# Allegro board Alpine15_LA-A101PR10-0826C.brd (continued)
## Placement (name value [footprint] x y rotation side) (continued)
CV2405  0.1U_0402_10V7K~D  [C_0402]  68.29 87.71 180 top
CV2406  0.1U_0402_10V7K~D  [C_0402]  68.29 85.87 180 top
CV2407  0.1U_0402_10V7K~D  [C_0402]  68.29 86.82 180 top
CV2408  0.1U_0402_10V7K~D  [C_0402]  65.36 82.69 180 top
CV2901  0.01U_0402_16V7K~D  [C_0402]  33.82 115.99 180 bottom
CV2902  0.01U_0402_16V7K~D  [C_0402]  31.81 113.17 0 top
CV2918  10U_0603_6.3V6M~D  [C_0603]  39.38 113.36 0 top
CV2919  10U_0603_6.3V6M~D  [C_0603]  39.51 113.36 180 bottom
CV2920  10U_0603_6.3V6M~D  [C_0603]  39.44 85.1 0 bottom
CV2921  10U_0603_6.3V6M~D  [C_0603]  25.22 94.69 90 top
CV2926  1U_0402_6.3V6K~D  [C_0402]  35.4 101 180 top
CV2927  1U_0402_6.3V6K~D  [C_0402]  36.47 114.12 180 top
CV2928  1U_0402_6.3V6K~D  [C_0402]  37.21 84.34 0 bottom
CV2929  1U_0402_6.3V6K~D  [C_0402]  28.64 101.04 180 top
CV2930  1U_0402_6.3V6K~D  [C_0402]  29.17 113.17 180 top
CV2931  1U_0402_6.3V6K~D  [C_0402]  38.41 101.11 0 top
CV2932  1U_0402_6.3V6K~D  [C_0402]  30.03 113.17 0 top
CV2933  1U_0402_6.3V6K~D  [C_0402]  38.44 113.17 180 top
CV2934  0.1U_0402_10V7K~D  [C_0402]  38.41 100.15 0 top
CV2935  0.1U_0402_10V7K~D  [C_0402]  36.47 113.17 180 top
CV2936  0.1U_0402_10V7K~D  [C_0402]  29.91 101.04 0 top
CV2937  0.1U_0402_10V7K~D  [C_0402]  37.17 100.98 180 top
CV2938  0.1U_0402_10V7K~D  [C_0402]  38.44 114.12 180 top
CV2939  0.1U_0402_10V7K~D  [C_0402]  37.17 100.03 180 top
CV2940  0.1U_0402_10V7K~D  [C_0402]  36.98 113.17 180 bottom
CV2941  0.01U_0402_16V7K~D  [C_0402]  33.59 113.17 0 top
CV2942  0.01U_0402_16V7K~D  [C_0402]  31.18 85.23 0 top
CV2943  0.01U_0402_16V7K~D  [C_0402]  33.4 97.61 0 top
CV2944  0.01U_0402_16V7K~D  [C_0402]  36.47 83.45 90 top
CV2945  0.1U_0402_10V7K~D  [C_0402]  28.28 113.17 180 bottom
CV2946  0.1U_0402_10V7K~D  [C_0402]  29.14 113.17 0 bottom
CV2947  0.1U_0402_10V7K~D  [C_0402]  28.28 114.06 180 bottom
CV2948  0.1U_0402_10V7K~D  [C_0402]  29.14 114.06 0 bottom
CV2949  0.1U_0402_10V7K~D  [C_0402]  29.17 114.06 180 top
CV2950  1U_0402_6.3V6K~D  [C_0402]  30.03 114.06 0 top
CV2951  1U_0402_6.3V6K~D  [C_0402]  30.29 84.28 0 bottom
CV2952  1U_0402_6.3V6K~D  [C_0402]  27.58 85.23 180 bottom
CV2953  0.1U_0402_10V7K~D  [C_0402]  35.58 84.34 180 bottom
CV2954  0.1U_0402_10V7K~D  [C_0402]  27.58 84.28 180 bottom
CV2955  0.1U_0402_10V7K~D  [C_0402]  30.29 85.23 0 bottom
CV2956  0.1U_0402_10V7K~D  [C_0402]  37.21 85.23 0 bottom
CV2957  0.1U_0402_10V7K~D  [C_0402]  35.58 85.23 180 bottom
CV2958  0.1U_0402_10V7K~D  [C_0402]  28.45 84.28 0 bottom
CV2959  1U_0402_6.3V6K~D  [C_0402]  28.45 85.23 0 bottom
CV2960  1U_0402_6.3V6K~D  [C_0402]  37.3 98.31 180 top
CV2961  1U_0402_6.3V6K~D  [C_0402]  27.58 84.28 180 top
CV2962  1U_0402_6.3V6K~D  [C_0402]  37.3 97.42 180 top
CV2963  0.1U_0402_10V7K~D  [C_0402]  38.41 97.36 0 top
CV2964  0.1U_0402_10V7K~D  [C_0402]  27.58 85.23 180 top
CV2965  0.1U_0402_10V7K~D  [C_0402]  38.41 99.2 0 top
CV2966  0.1U_0402_10V7K~D  [C_0402]  28.45 85.23 0 top
CV2967  0.1U_0402_10V7K~D  [C_0402]  30.24 85.24 270 top
CV2968  0.1U_0402_10V7K~D  [C_0402]  28.45 84.28 0 top
CV2969  1U_0402_6.3V6K~D  [C_0402]  38.41 98.25 0 top
CV3047  22U_0805_6.3V6M~D  [C_0805]  60.67 89.61 0 top
CV3048  4.7U_0603_6.3V6K~D  [C_0603]  60.28 92.09 0 top
CV3049  22U_0805_6.3V6M~D  [C_0805]  57.83 89.8 0 top
CV3050  22U_0805_6.3V6M~D  [C_0805]  54.91 89.8 0 top
CV3051  4.7U_0603_6.3V6K~D  [C_0603]  50 84.11 0 bottom
CV3052  22U_0805_6.3V6M~D  [C_0805]  52.91 80.24 0 top
CV3053  4.7U_0603_6.3V6K~D  [C_0603]  70.11 91.2 270 top
CV3054  4.7U_0603_6.3V6K~D  [C_0603]  66.31 94.63 90 top
CV3056  4.7U_0603_6.3V6K~D  [C_0603]  52.54 84.87 0 top
CV3057  22U_0805_6.3V6M~D  [C_0805]  53.33 86.69 0 top
CV3058  4.7U_0603_6.3V6K~D  [C_0603]  46.13 116.55 90 bottom
CV3059  22U_0805_6.3V6M~D  [C_0805]  51.46 116.53 90 bottom
CV3060  4.7U_0603_6.3V6K~D  [C_0603]  47.52 116.55 90 bottom
CV3061  4.7U_0603_6.3V6K~D  [C_0603]  61.48 106.19 90 top
CV3062  4.7U_0603_6.3V6K~D  [C_0603]  68.22 100.55 270 top
CV3063  22U_0805_6.3V6M~D  [C_0805]  69.87 100.45 270 top
CV3064  22U_0805_6.3V6M~D  [C_0805]  68.72 103.68 90 top
D1  RB751S40T1_SOD523-2~D  [RB751S40T1_SOD523-2]  17.23 119.29 180 bottom
D2  AZ5125-02S.R7G_SOT23-3  [AZ5125-02SPR7G_SOT23-3]  329.45 160.02 270 top
D12  RB751S40T1_SOD523-2~D  [RB751S40T1_SOD523-2]  311.17 176.19 0 bottom
D13  RB751S40T1_SOD523-2~D  [RB751S40T1_SOD523-2]  320.59 182.93 180 top
D14  RB751S40T1_SOD523-2~D  [RB751S40T1_SOD523-2]  328.95 176.12 90 bottom
D17  IP4292CZ10-TBR_XSON10_2.5X1~D  [IP4292CZ10-TBR_XSON10_2P5X1]  16.77 77.86 90 bottom
D18  PESD5V0U2BT_SOT23-3~D  [PESD5V0U2BT_SOT23-3]  16.6 80.83 270 top
D19  RB751S40T1_SOD523-2~D  [RB751S40T1_SOD523-2]  202.14 183.82 270 top
D20  PESD24VS2UT_SOT23-3~D  [PESD24VS2UT_SOT23-3]  151.65 183.45 0 bottom
D22  PESD5V0U2BT_SOT23-3~D  [PESD5V0U2BT_SOT23-3]  143.03 104.14 90 top
D23  RB751S40T1_SOD523-2~D  [RB751S40T1_SOD523-2]  220.68 39.03 0 top
D24  RB751S40T1_SOD523-2~D  [RB751S40T1_SOD523-2]  220.68 40.42 0 top
D27  -  [L30ESD24VC3-2_SOT23-3]  307.1 166 0 top
D65  RB751VM-40TE-17_SOD323-2~D  [RB751VM-40TE-17_SOD323-2]  14.05 102.35 0 top
D76  -  [BAT54CW_SOT323-3]  95.18 142.53 90 bottom
D77  PESD5V0U2BT_SOT23-3~D  [PESD5V0U2BT_SOT23-3]  104.54 158.03 90 top
D78  PESD5V0U2BT_SOT23-3~D  [PESD5V0U2BT_SOT23-3]  200.78 87.97 90 top
D79  -  [BAT54CW_SOT323-3]  129.18 124.5 270 top
D80  -  [BAT54CW_SOT323-3]  141.11 110.36 180 top
D87  PESD5V0U2BT_SOT23-3~D  [PESD5V0U2BT_SOT23-3]  208.96 170.73 90 top
D88  -  [L30ESDL5V0C3-2_SOT23-3]  99.58 164.78 0 bottom
DE1  -  [PESD5V0U2BT_SOT23-3]  234.63 131.58 90 top
DE2  -  [PESD5V0U2BT_SOT23-3]  234.63 127.62 90 top
FD1  FIDUCIAL MARK~D  [FIDUCIAL_C40M80]  5.3 10.32 180 bottom
FD2  FIDUCIAL MARK~D  [FIDUCIAL_C40M80]  86.38 185 0 top
FD3  FIDUCIAL MARK~D  [FIDUCIAL_C40M80]  225.67 12.64 0 top
FD4  FIDUCIAL MARK~D  [FIDUCIAL_C40M80]  328.23 145.3 180 bottom
H1  -  [H_4P4]  110.67 85.22 270 top
H2  -  [H_3P8]  110.67 65.22 90 top
H3  -  [H_4P4]  176.67 85.22 0 top
H4  -  [H_4P4]  176.67 65.22 0 top
H5  -  [H_3P8]  42.4 74.36 0 top
H6  -  [H_4P4]  77.58 125.33 0 top
H7  -  [H_3P0]  83.23 165.1 90 top
H8  -  [H_3P0]  141.7 177.95 90 top
H9  -  [H_3P0]  186.13 67.27 0 top
H10  -  [H_3P0]  6.12 117.82 0 top
H11  -  [H_3P0]  101.98 117.88 0 top
H12  -  [H_3P0]  231.9 108.6 0 top
H13  -  [H_3P0]  30.2 71.1 0 top
H14  -  [H_3P0]  229.7 177.95 90 top
H15  -  [H_3P0]  232.2 65.5 0 top
H16  -  [H_3P0]  11.8 3 0 top
H17  -  [H_3P0]  232.2 10.51 0 top
H18  -  [H_3P3]  341.9 186.6 0 top
H19  -  [H_3P3]  333.9 149.1 0 top
H20  -  [H_3P0]  188.2 3 0 top
H21  -  [H_2P5X4P0]  234.15 101.64 90 top
H22  -  [H_2P5X4P0]  82.23 182.21 0 top
H23  -  [H_1P2]  18.2 69.1 0 top
H24  -  [H_1P2]  89.98 61.52 0 top
H25  -  [H_1P2]  79.82 18.29 0 top
H26  -  [H_1P2]  286.35 165.2 0 top
H27  -  [H_1P2]  325.81 160.11 0 top
H28  -  [H_2P5X3P5]  6.3 3 90 top
H36  -  [H_3P3]  212.72 62.18 0 top
H37  -  [H_3P3]  106.7 164.1 0 top
H40  -  [H_3P0]  79.57 140.89 0 top
H41  -  [H_2P5N]  340.7 144.71 0 top
HDMIU1  -  [AP2330W-7_SC59-3]  16.65 99.61 270 top
JAPS1  ACES_50506-01841-P01  [ACES_50506-01841-P01_18P]  224.85 72.59 90 top
JBIO1  ACES_51524-0060N-001  [ACES_51524-0060N-001_6P]  203.26 85.1 90 top
JBT1  ACES_50273-0020N-001  [ACES_50273-0020N-001_2P-T]  12.19 22.48 90 bottom
JDEG1  TYCO_1-2041070-0~D  [TYCO_1-2041070-0_10P]  224.6 91.55 270 top
JDIMM1  CONCR_0706E0BE40F  [CONCR_0706E0BE40F_204P]  87.98 26.43 0 bottom
JDIMM2  CONCR_0706E0BE40F  [CONCR_0706E0BE40F_204P]  162.48 26.43 0 bottom
JDOCK1  JAE_WD2F144WB3R300~D  [JAE_WD2F144WB3R300_144P]  166.95 176.6 0 bottom
JEXP1  E&T_1001K-F40C-03L  [E-T_1001K-F40C-03L_40P]  97.12 22.67 0 top
JFAN1  ACES_50281-0040N-001  [ACES_50281-0040N-001_4P]  17.07 110.63 180 top
JHDMI1  CONCR_099BTAC19NBLCNF  [CONCR_099BTAC19NBLCNF_19P]  9.95 98.25 90 bottom
JIO1  E-T_1000-F80E-01L  [E-T_1000-F80E-01L_80P]  335.67 177.95 270 bottom
JKB1  ACES_51524-01001-003  [ACES_51524-01001-003_10P]  212.64 104.63 180 top
JLED1  ACES_51522-01201-001  [ACES_51522-01201-001_12P]  215.36 33.56 0 top
JLVDS1  ACES_50398-04071-001  [ACES_50398-04071-001_40P]  99.13 160.45 90 top
JMED1  ACES_51522-00601-001  [ACES_51522-00601-001_6P]  99.85 180.75 270 top
JMINI1  ACES_51700-0520W-001  [ACES_51700-0520W-001_52P]  301.9 188.2 0 bottom
JMINI2  LOTES_AAA-PCI-041-K01  [LOTES_AAA-PCI-041-K01_52P]  234.1 141.3 90 bottom
JPWR1  ACES_51522-01001-001  [ACES_51522-01001-001_10P]  314.75 169.02 180 top
JSATA1  J-L_TNBNRACB0007022  [J-L_TNBNRACB0007022_22P-T]  219.68 137 90 bottom
JSATA2  SANTA_201902-1  [SANTA_201902-1_13P]  237.54 22.21 270 bottom
JSD1  ALPS_SCDADA0101_NR  [ALPS_SCDADA0101_19P]  30.28 45.1 90 bottom
JSIM1  PROCO_879J-N006-00A0  [PROCO_879J-N006-00A0_8P]  258.99 186.49 0 bottom
JSPK1  ACES_50273-00401-001  [ACES_50273-00401-001_4P]  228.2 127.1 0 bottom
JTAA1  ACES_50051-02071-001  [ACES_50051-02071-001_20P-T]  206.01 76.23 0 bottom
JTAG1  @SHORT PADS~D  [SHORTPADS]  153.94 123.1 180 top
JTP1  ACES_51522-00801-001  [ACES_51522-00801-001_8P]  130.4 106.35 0 top
JTS1  E-T_4260K-Q06N-23L  [E-T_4260K-Q06N-23L_6P]  98.39 167.09 270 top
JUDB1  ACES_51522-02001-P02  [ACES_51522-02001-P02_20P]  107.65 134.27 270 top
JUSB1  SANTA_373130-1  [SANTA_373130-1_9P]  14.32 84.1 90 bottom
JXDP1  SAMTE_BSH-030-01-L-D-A  [SAMTE_BSH-030-01-L-D-A_60P]  95.21 37.36 90 top
L1  BLM18AG102SN1D_2P~D  [MURAT_BLM18AG102SN1D_2P]  177.34 170.34 0 bottom
L2  BLM18AG102SN1D_2P~D  [MURAT_BLM18AG102SN1D_2P]  180.23 168.09 90 bottom
L4  BLM18AG102SN1D_2P~D  [MURAT_BLM18AG102SN1D_2P]  177.39 168.82 0 bottom
L5  BLM18AG102SN1D_2P~D  [MURAT_BLM18AG102SN1D_2P]  174.68 168.31 0 bottom
L9  0_0402_5%~D  [R_0402]  15.61 103.39 180 bottom
L10  DLW21SN900HQ2L_0805_4P~D  [MURAT_DLW21SN900HQ2L_0805_4P]  16.01 103.39 180 bottom
L11  0_0402_5%~D  [R_0402]  15.61 104.25 180 bottom
L12  0_0402_5%~D  [R_0402]  15.66 106.74 180 bottom
L13  DLW21SN900HQ2L_0805_4P~D  [MURAT_DLW21SN900HQ2L_0805_4P]  16.05 106.77 180 bottom
L14  0_0402_5%~D  [R_0402]  15.66 107.63 180 bottom
L15  0_0402_5%~D  [R_0402]  15.61 100.77 180 bottom
L16  DLW21SN900HQ2L_0805_4P~D  [MURAT_DLW21SN900HQ2L_0805_4P]  16.01 100.79 180 bottom
L17  0_0402_5%~D  [R_0402]  15.61 101.66 180 bottom
L18  0_0402_5%~D  [R_0402]  15.66 98.18 180 bottom
L19  DLW21SN900HQ2L_0805_4P~D  [MURAT_DLW21SN900HQ2L_0805_4P]  16.05 98.19 180 bottom
L20  0_0402_5%~D  [R_0402]  15.66 99.05 180 bottom
L21  BLM21PG600SN1D_0805  [MURAT_BLM21PG600SN1D_2P]  323.74 154.48 90 bottom
L26  4.7UH_CBC2012T4R7M_20%~D  [TAIYO_CBC2012T4R7M_2P]  199.26 143.76 270 top
L27  0_0603_5%~D  [R0603_0OHM]  191.4 162.69 90 top
L28  0_0603_5%~D  [R0603_0OHM]  192.92 162.69 90 top
L29  0_0603_5%~D  [R0603_0OHM]  194.45 162.69 90 top
L30  0_0603_5%~D  [R0603_0OHM]  195.97 162.69 90 top
L31  0_0603_5%~D  [R0603_0OHM]  197.5 162.69 90 top
L32  0_0603_5%~D  [R0603_0OHM]  199.02 162.69 90 top
L33  0_0603_5%~D  [R0603_0OHM]  200.54 162.69 90 top
L34  0_0603_5%~D  [R0603_0OHM]  202.07 162.69 90 top
L35  BLM18BD601SN1D_0603~D  [MURAT_BLM18BD601SN1D_2P]  15.38 25.32 180 bottom
L36  BLM18BD601SN1D_0603~D  [MURAT_BLM18BD601SN1D_2P]  29.97 21.3 90 bottom
L37  0_0805_5%  [R0805_0OHM]  316.63 154.72 90 top
L40  DLW21SN900HQ2L_0805_4P~D  [MURAT_DLW21SN900HQ2L_0805_4P]  21.5 77.27 180 bottom
L41  DLW21SN900HQ2L_0805_4P~D  [MURAT_DLW21SN900HQ2L_0805_4P]  21.25 79.24 180 bottom
L42  DLW21SN900SQ2L_0805_4P~D  [MURAT_DLW21SN900SQ2L_0805_4P]  22.34 81.22 180 top
L43  DLW21SN900SQ2L_0805_4P~D  [MURAT_DLW21SN900SQ2L_0805_4P]  184.77 179.89 90 top
L44  0_0603_5%~D  [R0603_0OHM]  146.37 103.78 270 top
L45  0_0603_5%~D  [R0603_0OHM]  146.37 104.93 90 top
L46  DLW21SN900SQ2L_0805_4P~D  [MURAT_DLW21SN900SQ2L_0805_4P]  30.41 32.66 90 bottom
L47  DLW21SN900SQ2L_0805_4P~D  [MURAT_DLW21SN900SQ2L_0805_4P]  28.19 32.66 90 bottom
L48  DLW21SN900SQ2L_0805_4P~D  [MURAT_DLW21SN900SQ2L_0805_4P]  25.96 32.72 90 bottom
L49  BLM18PG471SN1D_2P~D  [MURAT_BLM18PG471SN1D_2P]  125.12 128.21 180 top
L50  BLM18PG471SN1D_2P~D  [MURAT_BLM18PG471SN1D_2P]  113.68 114.88 90 top
L51  BLM18PG471SN1D_2P~D  [MURAT_BLM18PG471SN1D_2P]  122.06 117.13 90 top
L52  DLW21SN900SQ2L_0805_4P~D  [MURAT_DLW21SN900SQ2L_0805_4P]  103.86 154.55 180 bottom
L53  DLW21SN900SQ2L_0805_4P~D  [MURAT_DLW21SN900SQ2L_0805_4P]  186.1 183.24 90 top
L54  OCF2012181YZF_4P  [SWLD_OCF2012181YZF_4P]  195.09 87.57 0 top
L55  DLW21SN900HQ2L_0805_4P~D  [MURAT_DLW21SN900HQ2L_0805_4P]  187.62 179.82 90 top
L56  DLW21SN900HQ2L_0805_4P~D  [MURAT_DLW21SN900HQ2L_0805_4P]  189.84 179.82 90 top
L57  DLW21SN900SQ2L_0805_4P~D  [MURAT_DLW21SN900SQ2L_0805_4P]  246.67 158.62 180 bottom
L58  DLW21SN900SQ2L_0805_4P~D  [MURAT_DLW21SN900SQ2L_0805_4P]  99.16 158.95 90 bottom
L59  DLW21SN900SQ2L_0805_4P~D  [MURAT_DLW21SN900SQ2L_0805_4P]  94.69 13.56 90 top
L69  0_0402_5%  [R0402_0OHM]  182.9 172.93 90 bottom
L70  0_0402_5%  [R0402_0OHM]  182.01 172.93 90 bottom
L71  0_0402_5%  [R0402_0OHM]  177.89 173.9 180 bottom
L72  DLW21SN900SQ2L_0805_4P~D  [MURAT_DLW21SN900SQ2L_0805_4P]  217.4 45.41 0 top
L73  BLM18PG300SN1D_2P~D  [MURAT_BLM18PG300SN1D_2P]  74.84 98.04 90 bottom
LC1  2.2UH +-20% LQM21PN2R2MC0D  [MURAT_LQM2MPN2R2NG0L_2P]  158.04 102.53 180 top
LC2  2.2UH +-20% LQM21PN2R2MC0D  [MURAT_LQM2MPN2R2NG0L_2P]  158.04 104.81 180 top
LC3  2.2UH_LQM2MPN2R2NG0L_30%  [MURAT_LQM2MPN2R2NG0L_2P]  161.94 96.98 270 top
LC4  2.2UH_LQM2MPN2R2NG0L_30%  [MURAT_LQM2MPN2R2NG0L_2P]  170.96 100.75 270 top
LC5  2.2UH_LQM2MPN2R2NG0L_30%  [MURAT_LQM2MPN2R2NG0L_2P]  161.64 99.1 180 top
LC6  2.2UH_LQM2MPN2R2NG0L_30%  [MURAT_LQM2MPN2R2NG0L_2P]  159.66 96.98 270 top
LE2  0_0603_5%~D  [R0603_0OHM]  129.94 123.32 270 top
LE3  0_0603_5%~D  [R0603_0OHM]  301.9 159.58 90 bottom
LE4  0_0603_5%~D  [R0603_0OHM]  303.42 159.58 90 bottom
LV74  BLM18AG121SN1D_2P  [MURAT_BLM18AG121SN1D_2P]  52.64 83.47 0 top
LV76  BLM18PG300SN1D_2P~D  [MURAT_BLM18PG300SN1D_2P]  55.14 85.09 270 top
LV80  BLM18PG181SN1D_2P  [MURAT_BLM18PG181SN1D_2P]  70.73 101.76 180 top
ME1  SHORT PADS~D  [SHORTPADS]  199.28 59.22 270 bottom
NOREF  -  []  110.67 65.22 0 top
NOREF#2  -  []  8.07 12.15 0 top
NOREF#3  -  []  168.34 33.95 0 top
NOREF#4  -  []  18.2 69.1 0 top
NOREF#5  -  []  110.67 85.22 0 top
NOREF#6  -  []  325.81 160.1 0 top
NOREF#7  -  []  231.9 108.79 0 top
NOREF#8  -  []  341.9 186.6 0 top
NOREF#9  -  []  101.98 117.88 0 top
NOREF#10  -  []  333.9 149.1 0 top
NOREF#11  -  []  176.67 85.22 0 top
NOREF#12  -  []  186.13 67.27 0 top
NOREF#13  -  []  30.2 71.1 0 top
NOREF#14  -  []  232.2 65.5 0 top
NOREF#15  -  []  229.7 177.95 0 top
NOREF#16  -  []  286.35 165.2 0 top
NOREF#17  -  []  186.78 43.65 0 top
NOREF#18  -  []  79.82 18.29 0 top
NOREF#19  -  []  176.67 65.22 0 top
NOREF#20  -  []  6.12 117.82 0 top
NOREF#21  -  []  141.71 177.95 0 top
NOREF#22  -  []  106.7 164.1 0 top
NOREF#23  -  []  85.48 61.51 0 top
NOREF#24  -  []  111.14 51.14 0 top
NOREF#25  -  []  144.47 32.04 0 top
NOREF#26  -  []  9.9 -34.89 0 top
NOREF#27  -  []  427.39 29.42 180 bottom
NOREF#28  -  []  127.88 41.52 180 bottom
NOREF#29  -  []  236.25 82.64 180 bottom
PBATT2  ACES_51996-00971-001  [ACES_51996-00971-001_9P]  107.89 185.3 0 bottom
PC3  2200P_0402_50V7K  [C_0402]  121.5 181.65 180 top
PC4  1500P_0402_50V7K  [C_0402]  134.76 138.11 270 top
PC5  0.022U_0603_50V7K  [C_0603]  127.48 144.91 0 top
PC6  0.1U_0603_25V7K  [C_0603]  92.4 171.15 180 bottom
PC9  10U_0805_25V6K  [C_0805]  92.56 172.62 180 bottom
PC10  0.1U_0603_25V7K  [C_0603]  93.82 170.57 90 bottom
PC11  0.1U_0603_25V7K  [C_0603]  101.87 172.69 90 top
PC12  0.1U_0603_25V7K  [C_0603]  96.54 149.45 90 bottom
PC51  1U_0603_10V6K  [C_0603]  209.74 151.71 90 top
PC52  10U_0805_25V6K  [C_0805]  220.09 155.54 270 top
PC53  0.1U_0402_25V6  [C_0402]  222.38 153.56 270 top
PC54  2200P_0402_50V7K  [C_0402]  221.49 153.56 270 top
PC55  0.1U_0402_25V6  [C_0402]  221.42 157.47 90 top
PC56  10U_0805_25V6K  [C_0805]  218.31 155.54 270 top
PC57  2200P_0402_50V7K  [C_0402]  222.31 157.47 90 top
PC58  10U_0805_25V6K  [C_0805]  218.31 156.76 90 top
PC59  10U_0805_25V6K  [C_0805]  220.09 156.76 90 top
PC60  0.1U_0603_25V7K  [C_0603]  213.1 161.55 270 top
PC61  0.1U_0603_25V7K  [C_0603]  212.98 152.6 270 top
PC62  680P_0603_50V7K  [C_0603]  228.17 147.23 180 top
PC65  680P_0603_50V7K  [C_0603]  224.85 163.58 180 top
PC67  0.1U_0603_25V7K  [C_0603]  233.44 163.61 0 top
PC68  0.1U_0603_25V7K  [C_0603]  216.79 153.17 270 top
PC69  1U_0603_10V6K  [C_0603]  216.79 156.09 270 top
PC70  1U_0603_10V6K  [C_0603]  211.07 160.35 180 top
PC71  220U_D2_6.3VY_R15M  [C_D2]  228.49 142.4 270 bottom
PC72  220U_D2_6.3VY_R15M  [C_D2]  230.01 165.9 180 bottom
PC100  10U_0805_25V6K  [C_0805]  46.37 19.18 270 bottom
PC101  10U_0805_25V6K  [C_0805]  46.37 21.41 90 bottom
PC102  0.1U_0402_25V6  [C_0402]  44.85 21.55 90 bottom
PC103  2200P_0402_50V7K  [C_0402]  44.97 18.91 270 bottom
PC104  0.22U_0603_16V7K  [C_0603]  43.75 17.14 180 bottom
PC105  10U_0805_6.3V6M  [C_0805]  42.1 11.58 270 bottom
PC106  10U_0805_6.3V6M  [C_0805]  43.88 11.58 270 bottom
PC107  1U_0603_10V6K  [C_0603]  40.82 18.15 180 bottom
PC109  680P_0603_50V7K  [C_0603]  53.62 10.17 180 bottom
PC111  1U_0603_10V6K  [C_0603]  36.05 18.12 180 bottom
PC112  0.033U_0402_16V7K  [C_0402]  40.25 10.61 270 bottom
PC113  100P_0402_50V8J  [C_0402]  38.27 10.61 270 bottom
PC114  0.1U_0402_10V7K  [C_0402]  36.95 10.61 270 bottom
PC115  0.1U_0402_10V7K  [C_0402]  34.8 14.28 180 bottom
PC116  330U_2.5V_M  [C_APXK2R5ARA331MF451]  68.29 19.75 90 bottom
PC150  4700P_0402_25V7K  [C_0402]  75.38 70.78 0 bottom
PC151  1U_0402_6.3V6K  [C_0402]  75.38 69.89 0 bottom
PC152  0.1U_0402_25V6  [C_0402]  76.85 64.5 270 bottom
PC153  2200P_0402_50V7K  [C_0402]  75.96 64.5 270 bottom
PC154  10U_0805_25V6K  [C_0805]  72.84 64.87 270 bottom
PC155  10U_0805_25V6K  [C_0805]  74.61 64.87 270 bottom
PC156  0.1U_0402_10V7K  [C_0402]  78.25 72.38 270 bottom
PC157  0.1U_0402_10V7K  [C_0402]  80.92 71.46 90 bottom
PC158  22U_0805_6.3VAM  [C_0805]  91.46 73.4 270 bottom
PC159  22U_0805_6.3VAM  [C_0805]  89.68 73.4 270 bottom
PC163  22U_0805_6.3VAM  [C_0805]  93.23 73.4 270 bottom
PC164  680P_0603_50V7K  [C_0603]  84.09 72.87 270 bottom
PC165  0.1U_0603_25V7K  [C_0603]  82.06 62.97 270 bottom
PC200  22U_0805_6.3VAM  [C_0805]  231.96 86.67 180 bottom
PC201  0.1U_0603_25V7K  [C_0603]  231.93 85.15 180 bottom
PC202  22P_0402_50V8J  [C_0402]  234.25 91.27 270 bottom
PC203  22U_0805_6.3VAM  [C_0805]  227.21 86.67 0 bottom
PC204  22U_0805_6.3VAM  [C_0805]  227.21 84.89 0 bottom
PC205  47P_0402_50V8J  [C_0402]  227.35 83.5 0 bottom
PC206  0.1U_0402_10V7K  [C_0402]  233.78 92.31 90 bottom
PC207  680P_0603_50V7K  [C_0603]  226.35 92.64 180 bottom
PC300  4700P_0603_50V7K  [C_0603]  85.63 95.74 180 bottom
PC301  0.1U_0402_10V7K  [C_0402]  87.45 94.95 90 bottom
PC302  0.1U_0402_25V6  [C_0402]  91.84 99.66 90 bottom
PC303  2.2U_0603_10V7K  [C_0603]  96.54 107.03 90 bottom
PC304  0.1U_0402_25V6  [C_0402]  91.55 107.09 0 bottom
PC305  100P_0402_50V8J  [C_0402]  88.28 88.18 270 bottom
PC306  1U_0603_10V6K  [C_0603]  79.45 85.89 180 bottom
PC307  680P_0603_50V7K  [C_0603]  97.62 103.8 180 top
PC308  1500P_0402_50V7K  [C_0402]  90.06 88.18 270 bottom
PC309  0.33U_0603_10V7K  [C_0603]  88.03 86.13 270 bottom
PC310  1U_0603_10V6K  [C_0603]  86.76 86.13 270 bottom
PC311  10U_0805_25V6K  [C_0805]  90.44 100.96 270 bottom
PC312  10U_0805_25V6K  [C_0805]  88.72 100.97 270 bottom
PC313  10U_0805_25V6K  [C_0805]  86.94 100.97 270 bottom
PC314  10U_0805_25V6K  [C_0805]  85.16 100.97 270 bottom
PC315  33U_D_25VM_R60M  [C_D]  87.73 112.46 180 bottom
PC316  33U_D_25VM_R60M  [C_D]  87.52 105.45 180 bottom
PC317  47P_0402_50V8J  [C_0402]  84.34 85.1 90 bottom
PC318  0.068U_0402_16V7K  [C_0402]  88.41 92.81 270 bottom
PC319  0.1U_0402_10V7K  [C_0402]  82.67 84.19 0 bottom
PC320  0.068U_0402_16V7K  [C_0402]  89.3 92.81 270 bottom
PC321  1000P_0402_50V7K  [C_0402]  78.85 40.01 0 bottom
PC322  0.1U_0402_25V6  [C_0402]  78.85 39.12 0 bottom
PC323  0.1U_0402_25V6  [C_0402]  60.84 39.38 180 bottom
PC324  1000P_0402_50V7K  [C_0402]  60.84 40.27 180 bottom
PC360  22U_0805_6.3VAM  [C_0805]  117.39 93.29 270 top
PC361  22U_0805_6.3VAM  [C_0805]  115.1 93.29 270 top
PC362  22U_0805_6.3VAM  [C_0805]  126.53 93.29 270 top
PC363  22U_0805_6.3VAM  [C_0805]  121.96 93.29 270 top
PC364  22U_0805_6.3VAM  [C_0805]  110.53 97.1 270 top
PC365  22U_0805_6.3VAM  [C_0805]  141.54 79.16 180 top
PC366  22U_0805_6.3VAM  [C_0805]  152.21 79.03 180 top
PC367  22U_0805_6.3VAM  [C_0805]  119.68 93.29 270 top
PC368  22U_0805_6.3VAM  [C_0805]  124.25 97.1 270 top
PC369  22U_0805_6.3VAM  [C_0805]  121.96 97.1 270 top
PC370  22U_0805_6.3VAM  [C_0805]  115.1 97.1 270 top
PC371  22U_0805_6.3VAM  [C_0805]  112.82 93.29 270 top
PC372  22U_0805_6.3VAM  [C_0805]  132.22 77.13 90 top
PC373  22U_0805_6.3VAM  [C_0805]  119.68 100.91 270 top
PC374  22U_0805_6.3VAM  [C_0805]  137.99 79.03 180 top
PC375  22U_0805_6.3VAM  [C_0805]  121.96 100.91 270 top
PC376  22U_0805_6.3VAM  [C_0805]  124.25 100.91 270 top
PC377  22U_0805_6.3VAM  [C_0805]  124.25 93.29 270 top
PC378  22U_0805_6.3VAM  [C_0805]  110.53 93.29 270 top
PC379  22U_0805_6.3VAM  [C_0805]  115.1 100.91 270 top
PC380  22U_0805_6.3VAM  [C_0805]  117.39 97.1 270 top
PC381  22U_0805_6.3VAM  [C_0805]  119.68 97.1 270 top
PC382  22U_0805_6.3VAM  [C_0805]  149.04 79.21 180 top
PC383  22U_0805_6.3VAM  [C_0805]  142.97 79.16 0 top
PC384  22U_0805_6.3VAM  [C_0805]  126.51 100.93 270 top
PC385  22U_0805_6.3VAM  [C_0805]  108.35 100.93 270 top
PC386  22U_0805_6.3VAM  [C_0805]  112.82 97.1 270 top
PC387  22U_0805_6.3VAM  [C_0805]  112.82 100.91 270 top
PC388  22U_0805_6.3VAM  [C_0805]  117.39 100.91 270 top
PC389  22U_0805_6.3VAM  [C_0805]  110.53 100.91 270 top
PC400  0.1U_0603_25V7K  [C_0603]  120.22 154.47 180 top
PC401  47P_0402_50V8J  [C_0402]  102.84 171.87 180 bottom
PC402  0.1U_0603_25V7K  [C_0603]  103.09 169.87 270 bottom
PC406  0.1U_0603_25V7K  [C_0603]  124.84 147.9 270 top
PC407  0.1U_0402_25V6  [C_0402]  118.99 156.58 90 top
PC408  0.1U_0402_25V6  [C_0402]  117.91 157.42 180 top
PC409  0.1U_0402_25V6  [C_0402]  115.81 157.49 270 top
PC410  1U_0603_10V6K  [C_0603]  114.95 163.74 180 top
PC411  10U_0805_25V6K  [C_0805]  113.78 155.93 90 top
PC412  0.1U_0603_25V7K  [C_0603]  101.82 169.87 270 bottom
PC413  0.1U_0402_25V6  [C_0402]  122.87 158.56 180 top
PC414  2200P_0402_50V7K  [C_0402]  102.84 170.98 180 bottom
PC415  22U_0805_25V6M  [C_0805]  104.62 169.83 270 bottom
PC416  22U_0805_25V6M  [C_0805]  106.39 169.83 270 bottom
PC417  0.047U_0603_25V7M  [C_0603]  112.7 161.1 0 top
PC418  1000P_0603_50V7K  [C_0603]  113.44 174.31 180 bottom
PC419  10U_0805_25V6K  [C_0805]  128.84 177.46 0 bottom
PC420  10U_0805_25V6K  [C_0805]  128.84 179.23 0 bottom
PC421  0.1U_0603_25V7K  [C_0603]  126.76 168.12 270 bottom
PC422  10U_0805_25V6K  [C_0805]  125.24 168.1 270 bottom
PC423  10U_0805_25V6K  [C_0805]  123.46 168.1 270 bottom
PC424  100P_0402_50V8J  [C_0402]  121.96 160.34 0 top
PC425  0.1U_0402_25V6  [C_0402]  116.07 166.37 270 top
PC426  0.1U_0402_25V6  [C_0402]  118.09 165.06 0 top
PC427  0.1U_0402_25V6  [C_0402]  119.88 165.1 90 top
PC428  100P_0402_50V8J  [C_0402]  115.06 135.15 270 top
PC429  0.01UF_0402_25V7K  [C_0402]  114.17 135.15 270 top
PC430  22U_0805_25V6M  [C_0805]  102.76 169.92 270 top
PC431  100P_0402_50V8J  [C_0402]  121.46 138.25 0 top
PC432  220P_0402_25V8J  [C_0402]  121.34 139.61 0 top
PC433  0.1U_0402_10V7K  [C_0402]  127.45 132.75 180 top
PC434  100P_0402_50V8J  [C_0402]  112.41 140.85 180 top
PC435  100P_0402_50V8J  [C_0402]  112.41 139.96 180 top
PC436  22U_0805_25V6M  [C_0805]  104.54 169.92 270 top
PC437  22U_0805_25V6M  [C_0805]  106.32 169.92 270 top
PC438  1U_0603_25V6  [C_0603]  116.35 154.47 0 top
PC439  1200P_0402_50V7K  [C_0402]  122.32 135.11 270 top
PC500  0.1U_0402_10V7K  [C_0402]  145.78 148.34 0 top
PC502  0.1U_0402_10V7K  [C_0402]  149.08 144.41 0 top
PC503  0.1U_0603_25V7K  [C_0603]  158.19 173.52 0 bottom
PC504  2200P_0402_50V7K  [C_0402]  158.31 172.25 0 bottom
PC505  0.47U_0805_25V6K  [C_0805]  156.86 172.08 270 top
PC506  0.01U_0603_25V7K  [C_0603]  131.97 177.56 270 bottom
PC507  0.1U_0402_10V7K  [C_0402]  155.26 155.02 270 top
PC508  0.1U_0402_10V7K  [C_0402]  155.21 159.24 270 top
PC509  1500P_0402_50V7K  [C_0402]  147.11 166.89 270 bottom
PC510  0.1U_0402_10V7K  [C_0402]  151.65 159.12 270 top
PC511  0.1U_0603_50V4Z  [C_0603]  128.08 149.17 270 top
PC512  0.1U_0603_25V7K  [C_0603]  130.7 149.45 270 top
PC513  0.047U_0603_25V7M  [C_0603]  135.44 152.09 0 top
PC514  0.1U_0402_25V6  [C_0402]  135.69 153.23 0 top
PC515  0.1U_0402_10V7K  [C_0402]  150.49 170.6 0 top
PC600  10U_0805_25VAK  [C_0805]  78.21 44.97 0 bottom
PC601  10U_0805_25VAK  [C_0805]  78.21 43.19 0 bottom
PC602  10U_0805_25V6K  [C_0805]  78.21 41.41 0 bottom
PC603  10U_0805_25V6K  [C_0805]  61.24 41.66 180 bottom
PC604  10U_0805_25VAK  [C_0805]  61.24 43.44 180 bottom
PC605  10U_0805_25VAK  [C_0805]  61.24 45.22 180 bottom
PC612  0.1U_0603_25V7K  [C_0603]  59.88 35 270 bottom
PC613  1U_0402_6.3V6K  [C_0402]  57.34 23.96 270 bottom
PC614  47P_0402_50V8J  [C_0402]  61.83 29.6 0 bottom
PC615  680P_0603_50V7K  [C_0603]  75.63 41.47 270 bottom
PC616  1800P_0402_50V7K  [C_0402]  60.02 21.22 180 bottom
PC617  1800P_0402_50V7K  [C_0402]  59.12 23.07 270 bottom
PC619  0.01UF_0402_25V7K  [C_0402]  56.44 22.11 0 bottom
PC620  33P_0402_50V8J  [C_0402]  52.77 23.05 90 bottom
PC621  0.1U_0402_10V7K  [C_0402]  57.8 34.66 270 bottom
PC622  470P_0402_50V7K  [C_0402]  51.88 25.14 90 bottom
PC623  47P_0402_50V8J  [C_0402]  52.77 25.14 90 bottom
PC624  0.01U_0402_16V7K  [C_0402]  52.77 27.83 270 bottom
PC625  0.01U_0402_16V7K  [C_0402]  52.84 30.93 180 bottom
PC626  0.01U_0402_16V7K  [C_0402]  52.84 29.98 180 bottom
PC627  0.1U_0603_25V7K  [C_0603]  55.05 35.12 270 bottom
PC628  680P_0603_50V7K  [C_0603]  45.66 40.77 270 bottom
PC660  4.7U_0603_6.3VAK  [C_0603]  59.7 96.28 90 top
PC661  4.7U_0603_6.3VAK  [C_0603]  56.43 101.21 180 top
PC662  4.7U_0603_6.3VAK  [C_0603]  55.7 96.15 180 top
PC663  4.7U_0603_6.3VAK  [C_0603]  59.77 100.66 270 top
PC664  4.7U_0603_6.3VAK  [C_0603]  61.73 101.04 270 top
PC665  4.7U_0603_6.3VAK  [C_0603]  58.88 104.03 90 top
PC666  4.7U_0603_6.3VAK  [C_0603]  61.54 96.34 90 top
PC667  4.7U_0603_6.3VAK  [C_0603]  57.42 103.52 180 top
PC668  4.7U_0603_6.3VAK  [C_0603]  63.26 99.58 0 top
PC669  4.7U_0603_6.3VAK  [C_0603]  62.94 101.3 0 top
PC670  0.1U_0402_10V7K  [C_0402]  57.48 100.23 270 top
PC671  0.1U_0402_10V7K  [C_0402]  60.39 103.01 0 top
PC672  0.1U_0402_10V7K  [C_0402]  63.31 96.79 0 top
PC673  0.1U_0402_10V7K  [C_0402]  57.68 97.61 180 top
PC674  47U_0805_4VAM  [C_0805]  59.21 54.36 0 bottom
PC675  22U_0805_6.3VAM  [C_0805]  64.41 54.36 180 bottom
PC676  4.7U_0603_6.3VAK  [C_0603]  59.18 56.01 0 bottom
PC677  4.7U_0603_6.3VAK  [C_0603]  59.18 57.28 0 bottom
PC678  4.7U_0603_6.3VAK  [C_0603]  64.39 57.41 180 bottom
PC679  4.7U_0603_6.3VAK  [C_0603]  67.83 59.92 90 bottom
PC680  4.7U_0603_6.3VAK  [C_0603]  64.39 56.01 180 bottom
PC683  330U_X_2VM_R6M  [C_X]  47.51 57.97 270 bottom
PC684  330U_X_2VM_R6M  [C_X]  73.47 58.33 0 bottom
PC700  0.1U_0402_25V6  [C_0402]  40.1 36.93 180 bottom
PC701  2200P_0402_50V7K  [C_0402]  40.1 36.04 180 bottom
PC702  10U_0805_25V6K  [C_0805]  40.57 34.6 180 bottom
PC703  10U_0805_25V6K  [C_0805]  40.57 32.83 180 bottom
PC704  0.1U_0603_25V7K  [C_0603]  37.55 33.18 180 bottom
PC705  680P_0603_50V7K  [C_0603]  34.56 40.61 270 bottom
PC706  1U_0402_6.3V6K  [C_0402]  32.61 30.67 270 bottom
PC708  0.1U_0402_10V7K  [C_0402]  33.88 26.4 270 bottom
PC709  330U_2.5V_M  [C_APXK2R5ARA331MF451]  41.44 55.61 0 bottom
PD1  -  [TVNST52302AB0_SOT523-3]  89.2 167.51 0 bottom
PD2  -  [TVNST52302AB0_SOT523-3]  89.02 169.86 0 bottom
PD4  -  [RB751VM-40TE-17_SOD323-2]  133.86 145.03 270 top
PD5  -  [BAV99W-7-F_SOT323-3]  129.8 136.37 180 top
PD300  -  [SDMK0340L-7-F_SOD323-2]  76.14 87.05 90 bottom
PD400  -  [BAT54CW_SOT323-3]  109.11 157.52 180 top
PD401  -  [BAT54HT1G_SOD323-2]  111.9 163.74 90 top
PD500  -  [PDS5100H-13_POWERDI5-3]  137.45 164.91 180 top
PD501  -  [SDMK0340L-7-F_SOD323-2]  142.99 161.17 180 top
PD502  -  [PDS5100H-13_POWERDI5-3]  130.38 167.42 0 bottom
PD503  -  [SDMK0340L-7-F_SOD323-2]  147.59 160.2 90 top
PD504  -  [SDMK0340L-7-F_SOD323-2]  151.19 149.18 90 top
PD505  -  [PDS5100H-13_POWERDI5-3]  155.02 167.55 180 bottom
PD506  -  [SDMK0340L-7-F_SOD323-2]  154.9 162.85 0 top
PD507  -  [SDMK0340L-7-F_SOD323-2]  139.51 152.85 270 top
PD508  -  [SDMK0340L-7-F_SOD323-2]  154.9 161.07 0 top
PD509  -  [SDMK0340L-7-F_SOD323-2]  129.28 164.34 180 top
PD510  -  [SDMK0340L-7-F_SOD323-2]  141.29 152.85 270 top
PD511  -  [SDMK0340L-7-F_SOD323-2]  129.35 162.37 270 top
PD512  -  [SDMK0340L-7-F_SOD323-2]  142.51 167.48 270 top
PD513  -  [SDMK0340L-7-F_SOD323-2]  148.99 171.93 0 top
PD514  -  [SDMK0340L-7-F_SOD323-2]  142.43 131.3 180 top
PD601  -  [SDMK0340L-7-F_SOD323-2]  67.05 32.27 180 bottom
PH300  100K_0402_1%_NCP15WF104F03RC  [R_0402]  93.92 107.35 0 bottom
PH301  10K_0402_1%_TSM0A103F34D1RZ  [R_0402]  94.3 95.54 0 bottom
PH302  10K_0402_1%_TSM0A103F34D1RZ  [R_0402]  46.43 45.85 180 bottom
PJP2  PAD-OPEN1x1m  [JUMP_43X39]  219.93 122.21 180 top
PJP3  PAD-OPEN1x1m  [JUMP_43X39]  223.97 112.31 90 bottom
PJP4  PAD-OPEN1x1m  [JUMP_43X39]  326.03 152.74 90 bottom
PJP5  PAD-OPEN1x1m  [JUMP_43X39]  184.24 146.6 180 top
PJP6  PAD-OPEN1x1m  [JUMP_43X39]  180.98 130.39 270 top
PJP7  PAD-OPEN1x1m  [JUMP_43X39]  169.55 138.45 270 top
PJP8  PAD-OPEN1x1m  [JUMP_43X39]  132.99 110.02 270 top
PJP9  PAD-OPEN1x1m  [JUMP_43X39]  224.22 121.22 90 bottom
PJP10  PAD-OPEN1x1m  [JUMP_43X39]  89.74 160.15 180 bottom
PJP11  PAD-OPEN1x1m  [JUMP_43X39]  155.21 99.3 270 top
PJP12  PAD-OPEN1x1m  [JUMP_43X39]  221.25 59.68 270 top
PJP13  PAD-OPEN1x1m  [JUMP_43X39]  91.28 166.41 180 bottom
PJP52  PAD-OPEN 1x3m  [JUMP_43X118]  230.31 164.85 90 top
PJP53  PAD-OPEN 1x3m  [JUMP_43X118]  224.68 145.2 180 bottom
PJP100  PAD-OPEN 1x2m~D  [JUMP_43X79]  42.04 20.76 0 bottom
PJP101  PAD-OPEN1x1m  [JUMP_43X39]  42.87 13.25 0 bottom
PJP102  JUMP_1x3m  [JUMP_43X118]  73.13 11.98 0 bottom
PJP103  JUMP_1x3m  [JUMP_43X118]  73.13 17.31 0 bottom
PJP104  PAD-OPEN1x1m  [JUMP_43X39]  45.46 11.37 0 bottom
PJP150  PAD-OPEN 1x2m~D  [JUMP_43X79]  73.94 67.46 180 bottom
PJP151  PAD-OPEN 1x3m  [JUMP_43X118]  94.28 67.59 0 bottom
PJP152  PAD-OPEN 1x2m~D  [JUMP_43X79]  94.93 79.92 180 bottom
PJP200  PAD-OPEN 1x2m~D  [JUMP_43X79]  230.41 80.79 90 bottom
PJP201  PAD-OPEN 1x2m~D  [JUMP_43X79]  226.47 81.89 270 bottom
PJP300  PAD-OPEN 4x4m  [JUMP_43X118]  93.53 112.31 180 bottom
PJP401  PAD-OPEN1x1m  [JUMP_43X39]  121.32 165.8 0 top
PJP600  -  [JUMP_43X118]  74.31 32.55 90 bottom
PJP601  PAD-OPEN 1x3m  [JUMP_43X118]  53.91 59.76 90 bottom
PJP602  PAD-OPEN 1x3m  [JUMP_43X118]  59.14 59.76 90 bottom
PJP603  PAD-OPEN 1x3m  [JUMP_43X118]  64.38 59.76 90 bottom
PJP700  PAD-OPEN 1x2m~D  [JUMP_43X79]  41.17 30.87 270 bottom
PJP701  PAD-OPEN 1x2m~D  [JUMP_43X79]  41.4 60.25 90 bottom
PJP702  PAD-OPEN 1x2m~D  [JUMP_43X79]  37.46 60.25 90 bottom
PJP802  PAD-OPEN1x1m  [JUMP_43X39]  230.6 36.61 180 top
PJP803  PAD-OPEN1x1m  [JUMP_43X39]  232.1 36.61 0 top
PJP804  PAD-OPEN1x1m  [JUMP_43X39]  263.54 155.41 90 bottom
PJP805  PAD-OPEN1x1m  [JUMP_43X39]  258.28 155.36 180 bottom
PJP806  PAD-OPEN1x1m  [JUMP_43X39]  214.27 180.45 270 top
PJP807  PAD-OPEN1x1m  [JUMP_43X39]  268.62 176.26 270 bottom
PJP808  PAD-OPEN1x1m  [JUMP_43X39]  271.78 174.64 0 bottom
PJPDC1  ACES_50481-0057N-001  [ACES_50481-0057N-001_5P]  92.11 153.89 270 bottom
PL1  FBMJ4516HS720NT_2P  [TAIYO_FBMJ4516HS720NT_2P]  131.06 182.18 0 top
PL2  FBMJ4516HS720NT_2P  [TAIYO_FBMJ4516HS720NT_2P]  131.06 184.6 0 top
PL3  BLM18BD102SN1D_2P  [MURAT_BLM18BD102SN1D_2P]  122.14 144.91 0 top
PL4  FBMA-L11-453215800LMA90T_2P  [KC_FBMA-L11-453215800LMA90T_2P]  95.51 169.47 0 bottom
PL5  FBMA-L11-453215800LMA90T_2P  [KC_FBMA-L11-453215800LMA90T_2P]  99.08 149.13 270 bottom
PL51  1UH_PCMB053T-1R0MS_7A_20%  [CYNTE_PCMB053T-1R0MS_2P]  216.33 167.84 0 bottom
PL52  2.2UH_ETQP3W2R2WFN_8.5A_20%  [PANAS_ETQP3W2R2WFN_2P]  230.02 151.29 0 bottom
PL53  2.2UH_ETQP3W2R2WFN_8.5A_20%  [PANAS_ETQP3W2R2WFN_2P]  224.3 159.04 180 bottom
PL100  2.2UH_ETQP3W2R2WFN_8.5A_20%  [PANAS_ETQP3W2R2WFN_2P]  62.87 14.59 0 bottom
PL150  0.68UH_TMPC0624H-R68MG-D_13A_20%  [TAI-T_TMPC0624H-R68MG-D_2P]  85.29 67.44 0 bottom
PL200  1UH_NRS4018T1R0NDGJ_3.2A_30%  [TAIYO_NRS4018T1R0NDGJ_2P]  226.29 89.72 180 bottom
PL300  0.22UH_FDUE0640J-H-R2_25A_20%  [TOKO_FDUE0640J-H-R22M-P3_4P]  99.83 101.66 270 bottom
PL400  1UH_PCMB053T-1R0MS_7A_20%  [CYNTE_PCMB053T-1R0MS_2P]  103.86 178.14 270 bottom
PL401  2.2UH_PCMB103T-2R2MS_13A_20%  [CYNTE_PCMB103T-2R2MS_2P]  119.52 179.39 270 bottom
PL601  0.22UH_FDUE0640J-H-R2_25A_20%  [TOKO_FDUE0640J-H-R22M-P3_4P]  69.41 48 90 bottom
PL602  0.22UH_FDUE0640J-H-R2_25A_20%  [TOKO_FDUE0640J-H-R22M-P3_4P]  54.88 48.11 90 bottom
PL700  1UH_FDSD0630-H-1R0M-P3_11A_20%  [TOKO_FDSD0630-H-1R0M-P3_2P]  39.21 44.22 90 bottom
PQ1  -  [DMG2301U-7_SOT23-3]  135.65 141.87 180 top
PQ2  -  [FDV301N-G_SOT23-3]  124.45 142.02 270 top
PQ3  -  [MMST3904-7-F_SOT323-3]  125.87 138.78 180 top
PQ4  -  [FDS6679AZ-G_SO8]  100.22 172.46 180 bottom
PQ5  -  [IMD2AGZT108_SC74-6]  128.83 141.17 270 top
PQ51  -  [SIS412DN-T1-GE3_POWERPAK8-5]  226.54 152.76 90 top
PQ52  -  [SIS412DN-T1-GE3_POWERPAK8-5]  226.54 156.37 90 top
PQ53  -  [SIS472DN-T1_POWERPAK1212-8-5]  223.67 151.11 270 top
PQ54  -  [SIS472DN-T1_POWERPAK1212-8-5]  223.67 162.03 270 top
PQ100  -  [SI4128DY-T1-GE3_SO8]  53.79 21.09 270 bottom
PQ101  -  [SI4134DY-T1-GE3_SO8]  48.47 11.9 90 bottom
PQ400  -  [AON7403L_DFN8-5]  100.34 181.78 270 bottom
PQ401  -  [NTR4502PT1G_SOT23-3]  113.98 149.46 0 top
PQ402  -  [NTR4502PT1G_SOT23-3]  118.04 149.46 0 top
PQ403  -  [SI3993CDV-T1-GE3_TSOP6]  121.06 151.58 270 top
PQ404  -  [SIR472DP-T1-GE3_POWERPAK8-5]  113.48 171.97 270 bottom
PQ406  -  [SIRA06DP-T1-GE_POWERPAKSO-8-5]  107.71 176.82 90 bottom
PQ409  -  [DMN66D0LDW-7_SOT363-6]  123.47 135.02 270 top
PQ410  -  [DMN65D8LW-7_SOT323-3]  118.38 134.4 270 top
PQ411  -  [DMN65D8LW-7_SOT323-3]  132.84 133.51 90 top
PQ500  -  [NTR4502PT1G_SOT23-3]  141.96 156.96 0 top
PQ501  -  [SI4835DDY-T1-GE3_SO8]  139.31 168.06 90 top
PQ502  -  [DMN66D0LDW-7_SOT363-6]  148 148.75 0 top
PQ503  -  [DMN66D0LDW-7_SOT363-6]  142.92 151.29 0 top
PQ504  -  [SI4835DDY-T1-GE3_SO8]  128.06 170.47 90 bottom
PQ505  -  [FDS6679AZ-G_SO8]  135.74 179.19 180 top
PQ506  -  [DMN66D0LDW-7_SOT363-6]  150.89 160.17 90 top
PQ507  -  [DMN66D0LDW-7_SOT363-6]  149.9 145.79 90 top
PQ508  -  [DMN65D8LW-7_SOT323-3]  147.66 139.99 90 top
PQ510  -  [FDS6679AZ-G_SO8]  156.61 174.41 270 bottom
PQ511  -  [FDS6679AZ-G_SO8]  144.68 171.87 270 bottom
PQ512  -  [DMN65D8LW-7_SOT323-3]  157.43 150.15 270 top
PQ514  -  [DMN65D8LW-7_SOT323-3]  153.07 155.1 0 top
PQ515  -  [DMN66D0LDW-7_SOT363-6]  138.41 140.56 0 top
PQ516  -  [DMN66D0LDW-7_SOT363-6]  148.54 158.6 180 top
PQ517  -  [NTR4502PT1G_SOT23-3]  137.76 147.98 180 top
PQ518  -  [DMG2301U-7_SOT23-3]  125.35 162.13 180 top
PQ519  -  [DMN66D0LDW-7_SOT363-6]  141.33 140.56 0 top
PQ520  -  [NTR4502PT1G_SOT23-3]  141.71 147.98 180 top
PQ521  -  [DMN65D8LW-7_SOT323-3]  148.66 154.49 0 top
PQ522  -  [NTR4502PT1G_SOT23-3]  135.19 159.9 270 top
PQ523  -  [DMN66D0LDW-7_SOT363-6]  138.03 155.23 0 top
PQ524  -  [FDMC6679AZ_MLP8-5]  146.7 170.26 90 bottom
PQ525  -  [AO3418_SOT23-3]  146.98 166.92 90 top
PQ526  -  [NTR4502PT1G_SOT23-3]  150.22 174.12 0 top
PQ527  -  [DMN65D8LW-7_SOT323-3]  149.47 166.84 0 top
PQ528  -  [DMN65D8LW-7_SOT323-3]  145.09 133.09 0 top
PQ529  -  [DMN65D8LW-7_SOT323-3]  138.13 133.51 90 top
PQ600  -  [SIR472DP-T1-GE3_POWERPAK8-5]  74.02 47.51 90 bottom
PQ601  -  [SIRA06DP-T1-GE_POWERPAKSO-8-5]  68.39 39.88 180 bottom
PQ602  -  [SIRA06DP-T1-GE_POWERPAKSO-8-5]  73.98 39.88 180 bottom
PQ603  -  [SIR472DP-T1-GE3_POWERPAK8-5]  59.49 47.51 90 bottom
PQ604  -  [SIRA06DP-T1-GE_POWERPAKSO-8-5]  57.34 40.01 180 bottom
PQ605  -  [SIRA06DP-T1-GE_POWERPAKSO-8-5]  51.62 40.01 180 bottom
PQ700  -  [SIS412DN-T1-GE3_POWERPAK8-5]  40.43 41.03 0 bottom
PQ701  -  [SI7716ADN-T1-GE3_POWERPAK8-5]  38.35 38.16 180 bottom
PQ702  -  [DMN66D0LDW-7_SOT363-6]  128.93 128.03 0 top
PR2  100K_0402_5%  [R_0402]  133.21 146.44 0 top
PR3  100_0402_5%  [R_0402]  88.57 172.16 90 bottom
PR4  100_0402_5%  [R_0402]  87.76 169.32 270 bottom
PR5  100_0402_5%  [R_0402]  89.46 172.16 90 bottom
PR8  2.2K_0402_5%  [R_0402]  131.33 139.71 180 top
PR9  33_0402_5%  [R_0402]  128.51 139.71 0 top
PR10  100K_0402_1%  [R_0402]  124.14 139.02 270 top
PR11  10K_0402_1%  [R_0402]  127.57 138.11 90 top
PR12  15K_0402_1%  [R_0402]  124.14 137.12 270 top
PR13  10K_0402_5%  [R_0402]  127.57 137.12 270 top
PR14  1M_0402_5%  [R_0402]  127.37 146.31 0 top
PR18  100K_0402_5%  [R_0402]  91.93 170.1 180 bottom
PR19  4.7K_0805_5%  [R_0805]  100.35 172.54 90 top
PR20  10K_0402_5%  [R_0402]  130.49 144.84 90 top
PR21  1M_0402_5%  [R_0402]  95.2 172.16 90 bottom
PR51  6.49K_0402_1%  [R_0402]  209.03 155.01 0 top
PR52  15.4K_0402_1%  [R_0402]  209.94 157.74 180 top
PR53  10K_0402_5%  [R_0402]  209.03 155.96 0 top
PR55  10K_0402_5%  [R_0402]  209.94 156.85 180 top
PR56  95.3K_0402_1%  [R_0402]  209.03 154.06 0 top
PR57  105K_0402_1%  [R_0402]  209.03 158.63 0 top
PR58  100K_0402_5%  [R_0402]  211 152.65 270 top
PR59  200_0402_1%  [R_0402]  211.98 160.11 90 top
PR60  0_0402_5%  [R0402_0OHM]  211.89 151.73 90 top
PR61  2.2_0603_5%  [R_0603]  214.37 160.15 90 top
PR62  2.2_0603_5%  [R_0603]  214.25 151.2 90 top
PR63  4.7_1206_5%  [R_1206]  225.63 147.23 180 top
PR64  4.7_1206_5%  [R_1206]  221.93 163.77 270 top
PR65  0_0402_5%  [R0402_0OHM]  210.17 161.42 0 top
PR100  2.2_0603_5%  [R_0603]  43.75 15.87 180 bottom
PR101  19.6K_0402_1%  [R_0402]  37.28 17.06 0 bottom
PR102  5.1_0603_5%  [R_0603]  38.41 18.15 180 bottom
PR103  4.7_1206_5%  [R_1206]  50.96 10.04 180 bottom
PR104  100K_0402_5%  [R_0402]  33.89 16.95 0 bottom
PR105  8.06K_0402_1%  [R_0402]  39.16 10.61 270 bottom
PR106  1M_0402_1%  [R_0402]  33.89 16.06 0 bottom
PR107  0_0402_5%  [R_0402]  33.89 15.17 0 bottom
PR108  0_0402_5%  [R0402_0OHM]  33.89 13.39 0 bottom
PR109  10K_0402_1%  [R_0402]  35.55 10.61 270 bottom
PR110  0_0402_5%  [R0402_0OHM]  33.89 12.5 0 bottom
PR111  0_0402_5%  [R_0402]  33.89 11.61 0 bottom
PR150  0_0402_5%  [R0402_0OHM]  78.88 67.73 270 top
PR153  0_0402_5%  [R_0402]  79.14 72.38 270 bottom
PR154  0_0402_5%  [R0402_0OHM]  80.03 72.38 270 bottom
PR155  4.7_1206_5%  [R_1206]  88.09 72.17 180 bottom
PR156  100K_0402_5%  [R_0402]  81.8 72.38 270 bottom
PR157  0_0402_5%  [R0402_0OHM]  82.82 71.46 90 bottom
PR158  5.1_0603_5%  [R_0603]  83.33 62.97 270 bottom
PR201  7.68K_0805_1%  [R_0805]  228.03 91.49 90 bottom
PR202  30.1K_0402_1%  [R_0402]  235.14 91.27 270 bottom
PR203  0_0402_5%  [R_0402]  232 93.22 270 bottom
PR204  20K_0402_1%  [R_0402]  234.25 89.5 270 bottom
PR205  1M_0402_5%  [R_0402]  232.89 92.31 90 bottom
PR206  0_0402_5%  [R0402_0OHM]  231.11 93.22 270 bottom
PR300  75_0402_1%  [R_0402]  89.09 85.31 0 bottom
PR301  390K_0402_1%  [R_0402]  85.05 94.58 180 bottom
PR302  75_0402_1%  [R_0402]  82.31 95.93 270 bottom
PR303  1M_0402_1%  [R_0402]  79.64 95.93 270 bottom
PR304  9.31K_0402_1%  [R_0402]  78.75 95.93 270 bottom
PR305  10K_0402_5%  [R_0402]  86.56 94.95 90 bottom
PR306  75K_0402_1%  [R_0402]  83.2 95.01 90 bottom
PR307  150K_0402_1%  [R_0402]  81.42 95.01 90 bottom
PR308  150K_0402_1%  [R_0402]  80.53 95.01 90 bottom
PR309  150K_0402_1%  [R_0402]  77.87 95.01 90 bottom
PR310  39K_0402_5%  [R_0402]  88.34 94.95 90 bottom
PR311  10K_0402_5%  [R_0402]  89.23 95.86 270 bottom
PR312  0_0402_5%  [R0402_0OHM]  79.91 93.63 180 bottom
PR313  0_0402_5%  [R_0402]  79.91 92.74 180 bottom
PR314  75_0402_1%  [R_0402]  77.09 91.85 0 bottom
PR315  0_0402_5%  [R0402_0OHM]  79.91 91.85 180 bottom
PR317  0_0402_5%  [R0402_0OHM]  79.91 89.4 180 bottom
PR318  0_0402_5%  [R_0402]  79.91 90.29 180 bottom
PR319  1.91K_0402_1%  [R_0402]  79.9 88.14 180 bottom
PR320  1_0603_5%  [R_0603]  79.77 87.1 180 bottom
PR321  0_0603_5%  [R_0603]  92.71 108.36 180 bottom
PR322  2.43K_0402_1%  [R_0402]  90.01 86.2 180 bottom
PR323  10K_0402_5%  [R_0402]  89.17 88.18 270 bottom
PR324  4.7_1206_5%  [R_1206]  101.55 103.8 180 top
PR325  5.62K_0402_1%  [R_0402]  89.22 89.12 0 bottom
PR326  0_0402_5%  [R0402_0OHM]  83.45 86.02 270 bottom
PR327  10_0603_1%  [R_0603]  85.49 84.74 90 bottom
PR328  2.4K_0402_1%  [R_0402]  95.22 96.43 180 bottom
PR329  3.01K_0402_1%  [R_0402]  95.22 94.65 180 bottom
PR330  130_0402_1%  [R_0402]  80.79 85.1 90 bottom
PR331  54.9_0402_1%  [R_0402]  82.56 85.1 90 bottom
PR333  30K_0402_1%  [R_0402]  93.36 96.13 270 bottom
PR334  0_0402_5%  [R0402_0OHM]  90.13 90.01 180 bottom
PR335  0_0402_5%  [R0402_0OHM]  90.13 90.9 180 bottom
PR400  0.01_1206_1%  [R_1206_4P-D]  101.4 181.37 0 bottom
PR402  0_0402_5%  [R0402_0OHM]  119.24 143.07 0 top
PR403  0_0402_5%  [R0402_0OHM]  120.03 153.42 180 top
PR404  150K_0402_1%  [R_0402]  120.15 143.96 180 top
PR405  100K_0402_1%  [R_0402]  119.24 144.85 0 top
PR408  44.2_0402_1%  [R_0402]  120.09 146.76 180 top
PR410  10K_0402_5%  [R_0402]  117.87 156.37 180 top
PR411  59_0402_1%  [R_0402]  120.09 147.71 180 top
PR417  100K_0402_5%  [R_0402]  122.69 154.31 180 top
PR418  100K_0402_5%  [R_0402]  122.69 153.42 180 top
PR420  10_1206_5%  [R_1206]  111.18 159.45 0 top
PR421  316K_0402_1%  [R_0402]  122.87 157.67 180 top
PR422  4.02K_0402_1%  [R_0402]  119.88 156.58 90 top
PR423  2.2_0603_5%  [R_0603]  114.37 162.43 180 top
PR424  49.9K_0402_1%  [R_0402]  122.87 159.45 180 top
PR425  100K_0402_1%  [R_0402]  115 165.16 180 top
PR426  0.01_1206_1%  [R_1206_4P-D]  125.87 174.62 270 bottom
PR427  0_0402_5%  [R0402_0OHM]  115 166.94 180 top
PR428  121K_0402_1%  [R_0402]  114.09 166.05 0 top
PR429  0_0402_5%  [R0402_0OHM]  122.98 161.2 180 top
PR430  0_0402_5%  [R0402_0OHM]  122.98 162.09 180 top
PR431  10K_0402_5%  [R_0402]  122.9 163.11 180 top
PR432  4.02K_0402_1%  [R_0402]  121.96 164.02 0 top
PR433  4.7_1206_5%  [R_1206]  110.65 173.93 180 bottom
PR435  221K_0402_1%  [R_0402]  121.3 134.2 90 top
PR437  1.8M_0402_1%  [R_0402]  121.46 140.91 0 top
PR440  150K_0402_1%  [R_0402]  122.38 136.47 180 top
PR441  20K_0402_1%  [R_0402]  122.38 141.8 180 top
PR442  0_0402_5%  [R0402_0OHM]  121.83 133.13 180 top
PR443  150K_0402_1%  [R_0402]  119.65 135.11 270 top
PR444  66.5K_0402_1%  [R_0402]  121.46 137.36 0 top
PR445  232K_0402_1%  [R_0402]  111.49 141.74 0 top
PR446  48.7K_0402_1%  [R_0402]  111.49 138.18 0 top
PR447  1M_0402_1%  [R_0402]  111.49 136.41 0 top
PR448  10K_0402_1%  [R_0402]  111.49 137.29 0 top
PR449  100K_0402_5%  [R_0402]  129.92 133.22 90 top
PR450  0_0402_5%  [R0402_0OHM]  112.41 135.52 180 top
PR451  22.6K_0402_1%  [R_0402]  113.65 141.74 0 top
PR452  42.2K_0402_1%  [R_0402]  112.41 139.07 180 top
PR453  10K_0402_1%  [R_0402]  112.41 134.63 180 top
PR500  100K_0402_5%  [R_0402]  151.45 147.4 270 top
PR501  240K_0402_5%  [R_0402]  142.48 154.95 0 top
PR502  100K_0402_5%  [R_0402]  144.92 161.63 90 top
PR503  100K_0402_5%  [R_0402]  140.7 154.95 0 top
PR504  100K_0402_5%  [R_0402]  146.62 150.71 270 top
PR505  100K_0402_5%  [R_0402]  145.6 153.12 270 top
PR506  100K_0402_5%  [R_0402]  146.32 142.61 270 top
PR507  10K_0402_5%  [R_0402]  145.81 162.55 270 top
PR508  100K_0402_5%  [R_0402]  150.97 162.6 180 top
PR509  330K_0402_5%  [R_0402]  131.85 164.17 180 top
PR510  820_0603_1%  [R_0603]  131.97 178.51 90 bottom
PR513  0_0402_5%  [R0402_0OHM]  156.86 169.4 270 top
PR514  0_0402_5%  [R0402_0OHM]  146.32 139.41 90 top
PR516  330K_0402_5%  [R_0402]  152.09 175.68 0 bottom
PR517  100K_0402_5%  [R_0402]  146.22 166.89 270 bottom
PR518  100K_0402_5%  [R_0402]  157.06 151.93 180 top
PR519  0_0402_5%  [R0402_0OHM]  157.17 156.12 0 top
PR520  10K_0402_5%  [R_0402]  145.28 166.05 180 bottom
PR521  100K_0402_5%  [R_0402]  151.45 156.25 0 top
PR522  100K_0402_5%  [R_0402]  154.02 150.91 180 top
PR523  0_0402_5%  [R0402_0OHM]  154.14 156.25 180 top
PR524  240K_0402_5%  [R_0402]  136.13 144.15 0 top
PR525  10K_0402_5%  [R_0402]  141.16 133.77 270 top
PR526  100K_0402_5%  [R_0402]  139.14 139.01 180 top
PR527  100K_0402_5%  [R_0402]  125.67 157.43 90 top
PR528  100K_0402_5%  [R_0402]  138.03 144.15 0 top
PR529  0_0402_5%  [R0402_0OHM]  124.75 153.92 0 top
PR530  0_0402_5%  [R_0402]  124.75 153.04 0 top
PR531  0_0402_5%  [R0402_0OHM]  125.66 154.81 180 top
PR532  100K_0402_5%  [R_0402]  146.62 154.11 90 top
PR533  47_0805_5%  [R_0805]  126.43 147.49 90 top
PR534  0_0402_5%  [R0402_0OHM]  125.67 156.59 180 top
PR535  240K_0402_5%  [R_0402]  140.32 144.15 0 top
PR536  0_0402_5%  [R0402_0OHM]  127.77 161.12 90 top
PR537  10K_0402_5%  [R_0402]  130.81 161.92 90 top
PR538  100K_0402_5%  [R_0402]  129.3 146.65 90 top
PR539  100K_0402_5%  [R_0402]  142.19 139.01 180 top
PR540  240K_0402_5%  [R_0402]  148.62 167.97 0 top
PR541  0_0402_5%  [R0402_0OHM]  129.3 148.47 90 top
PR542  0_0402_5%  [R0402_0OHM]  131.97 148.3 90 top
PR543  0_0402_5%  [R0402_0OHM]  127.76 159.38 90 top
PR544  100K_0402_5%  [R_0402]  142.23 144.15 0 top
PR545  0_0402_5%  [R0402_0OHM]  130.68 159.63 90 top
PR546  0_0402_5%  [R0402_0OHM]  131.57 159.63 90 top
PR547  1M_0402_5%  [R_0402]  131.7 161.92 90 top
PR548  0_0402_5%  [R0402_0OHM]  133.79 148.27 90 top
PR549  0_0402_5%  [R0402_0OHM]  132.46 159.63 90 top
PR550  0_0402_5%  [R0402_0OHM]  134.68 148.27 90 top
PR551  0_0402_5%  [R_0402]  133.35 159.63 90 top
PR552  0_0402_5%  [R0402_0OHM]  135.69 156.03 0 top
PR553  0_0402_5%  [R0402_0OHM]  135.69 156.92 0 top
PR554  240K_0402_5%  [R_0402]  139 161.37 270 top
PR555  47K_0402_5%  [R_0402]  139 159.47 270 top
PR556  1M_0402_5%  [R_0402]  135.69 155.14 0 top
PR557  100K_0402_5%  [R_0402]  137.86 152.84 90 top
PR558  0_0402_5%  [R0402_0OHM]  135.69 154.25 0 top
PR559  0_0402_5%  [R0402_0OHM]  125.67 155.7 180 top
PR560  0_0402_5%  [R0402_0OHM]  144.16 140.32 270 top
PR561  0_0402_5%  [R_0402]  144.16 141.69 90 top
PR562  0_0402_5%  [R0402_0OHM]  153.1 151.93 0 top
PR563  0_0402_5%  [R_0402]  145.18 141.69 90 top
PR564  0_0402_5%  [R0402_0OHM]  145.18 140.32 270 top
PR565  100K_0402_5%  [R_0402]  149.74 178.01 0 top
PR566  0_0402_5%  [R0402_0OHM]  142.42 132.61 0 top
PR567  0_0402_5%  [R0402_0OHM]  124.78 157.43 90 top
PR568  0_0402_5%  [R_0402]  148.71 170.6 0 top
PR600  0_0402_5%  [R_0402]  62.75 26.93 180 bottom
PR601  2.2_0603_1%  [R_0603]  61.15 33.6 90 bottom
PR602  0_0402_5%  [R_0402]  61.83 26.04 0 bottom
PR603  10K_0402_5%  [R_0402]  62.75 27.82 180 bottom
PR604  30K_0402_1%  [R_0402]  58.23 23.96 270 bottom
PR606  4.7_1206_5%  [R_1206]  75.82 45.41 270 bottom
PR607  3K_0402_1%  [R_0402]  60.01 22.16 90 bottom
PR608  39K_0402_1%  [R_0402]  59.11 24.01 0 bottom
PR610  24K_0402_1%  [R_0402]  59.07 19.25 180 bottom
PR611  3K_0402_1%  [R_0402]  58.15 20.2 0 bottom
PR614  510K_0402_1%  [R_0402]  56.45 23.05 90 bottom
PR615  0_0402_5%  [R0402_0OHM]  54.54 23.05 90 bottom
PR616  100_0402_5%  [R_0402]  53.66 23.05 90 bottom
PR617  2.2_0603_1%  [R_0603]  56.32 33.73 90 bottom
PR618  0_0402_5%  [R0402_0OHM]  49.09 24.17 0 bottom
PR619  0_0402_5%  [R_0402]  50.91 23.19 0 bottom
PR620  100_0402_5%  [R_0402]  49.09 23.28 0 bottom
PR621  0_0402_5%  [R_0402]  50.91 24.07 0 bottom
PR622  15.8K_0402_1%  [R_0402]  50.99 26.06 270 bottom
PR623  25.5K_0402_1%  [R_0402]  50.1 26.92 90 bottom
PR624  470K_0402_1%  [R_0402]  51.88 27.83 270 bottom
PR625  866_0402_1%  [R_0402]  50.99 27.83 270 bottom
PR626  10K_0402_5%  [R_0402]  51.93 31.82 0 bottom
PR627  0_0402_5%  [R0402_0OHM]  62.75 32.3 180 bottom
PR628  10K_0402_5%  [R_0402]  53.05 28.79 180 bottom
PR630  2.2_0603_1%  [R_0603]  50.94 30.68 180 bottom
PR631  2.2_0603_1%  [R_0603]  53.78 33.73 90 bottom
PR632  4.7_1206_5%  [R_1206]  45.97 44.65 270 bottom
PR633  0_0402_5%  [R_0402]  52.84 32.71 180 bottom
PR634  15.4K_0402_1%  [R_0402]  62.75 28.71 180 bottom
PR635  7.87K_0402_1%  [R_0402]  58.69 33.74 90 bottom
PR636  2.2_0402_1%  [R_0402]  50.89 28.87 180 bottom
PR637  0_0402_5%  [R_0402]  48.48 28.1 180 bottom
PR701  2.2_0603_5%  [R_0603]  37.43 30.64 90 bottom
PR702  40.2K_0402_1%  [R_0402]  36.67 25.48 90 bottom
PR703  0_0402_5%  [R_0402]  34.77 25.48 90 bottom
PR704  0_0402_5%  [R0402_0OHM]  35.66 25.48 90 bottom
PR705  470K_0402_1%  [R_0402]  32.61 27.82 90 bottom
PR706  4.7_1206_5%  [R_1206]  34.57 37.98 270 bottom
PR707  9.31K_0402_1%  [R_0402]  32.1 26.4 270 bottom
PR708  10K_0402_1%  [R_0402]  32.99 26.4 270 bottom
PR709  0_0402_5%  [R0402_0OHM]  37.43 28.48 270 bottom
PR710  0_0402_5%  [R0402_0OHM]  31.75 29.44 180 bottom
PR711  0_0402_5%  [R_0402]  31.75 30.33 180 bottom
PU1  -  [TS5A63157DCKR_SC70-6]  132.92 138.04 180 top
PU51  -  [TPS51225CRUKR_QFN20_3X3]  211.74 157.21 270 top
PU100  -  [G5616ARZ1U_TQFN20_3X3]  39.21 12.27 180 bottom
PU150  -  [TPS51362RVER_QFN28_4P5X3P5]  82.12 68.47 270 bottom
PU200  -  [SYN470DBC_DFN10_3X3]  229.76 88.85 90 bottom
PU300  -  [TPS51622RSM_QFN32_4X4]  82.24 88.92 90 bottom
PU301  -  [CSD97374CQ4M_SON8_3P5X4P5]  95.01 105.7 270 bottom
PU401  -  [INA199A1DCKR_SC70-6]  123.53 146.61 90 top
PU402  -  [BQ24717RGRR_QFN20_3P5X3P5]  117.23 159.5 0 top
PU403  -  [LM358DR2G_SO8]  117.45 143.2 90 top
PU404  -  [LM393DR_SO8]  119.55 136.6 90 top
PU405  -  [74AHC1G08GW_SOT353-5]  128.78 133.79 90 top
PU500  -  [74AHC1G08GW_SOT353-5]  144.65 147.09 270 top
PU502  -  [74AHC1G08GW_SOT353-5]  147.96 143.28 270 top
PU503  -  [74AHC1G08GW_SOT353-5]  156.38 153.11 0 top
PU504  -  [74AHC1G08GW_SOT353-5]  156.38 157.3 0 top
PU505  -  [74AHC1G08GW_SOT353-5]  152.83 157.3 0 top
PU506  -  [74AHC1G08GW_SOT353-5]  151.12 167.36 0 top
PU600  -  [RT8813AGQW_WQFN24_4X4]  59.19 30.09 270 bottom
PU700  RT8237EZQW(2)_WDFN10_3X3  [RT8237EZQW-2_WDFN10_3X3]  35.83 28.26 180 bottom
PU701  -  [CD3301BRHHR_QFN36_6X6]  128.65 151.8 0 top
Q5  DMN66D0LDW-7_SOT363-6~D  [DMN66D0LDW-7_SOT363-6]  199.21 133.23 180 top
Q9  -  [L2N7002WT1G_SC-70-3]  116.64 78.09 90 top
